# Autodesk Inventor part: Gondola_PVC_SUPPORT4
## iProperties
Shininess: 64.0
Length Units: 11272
Angle Units: 11279
Time Units: 11290
Mass Units: 11286
Length Display Precision: 3
Angle Display Precision: 2
Compacted: True
Part Number: Gondola_PVC_SUPPORT4
Document SubType Name: Modeling
Created: 2004-08
Designer: John Blackburn
Manufacturer: Standard
Standards Organization: Custom
Material: PVC-Piping
Density: 0.0
Volumn: 0.0
Area: 0.0
PropertySet Name: Model Information
Control State: 0
Master: False
Checked Out: False
Author: John Blackburn
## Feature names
1. Base1
